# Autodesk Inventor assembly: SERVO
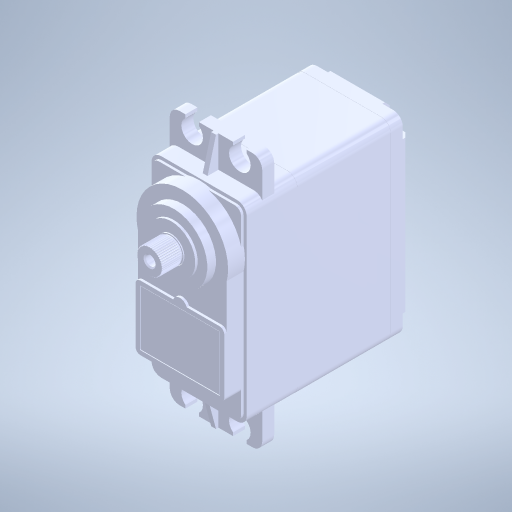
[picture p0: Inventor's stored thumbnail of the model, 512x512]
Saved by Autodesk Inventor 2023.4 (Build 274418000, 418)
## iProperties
Created: 2014-01
Part Number: SERVO
Description: SolidWorks IGES file using NURBS representation for surfaces
Document SubType Name: Assembly
Designer: mel
Title: C:\Users\Utente\Desktop\SERVO.IGS
Author: Utente
Sending System: SolidWorks 2012
Preprocessor: SolidWorks 2012
Minimum Resolution: 0.0
Sending System Product ID: SERVO.SLDASM
Receiving System Product ID: SERVO.SLDASM
Sent Units: Millimeter
Translation Standard: IGES 5.3
Model Creation Time: 2014-01-11
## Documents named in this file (3)
- D:\travail\année 2023-2024\IT\char à voile\hitec-hs-485hb-1.snapshot.2\SERVO\SERVO.iam
- D:\travail\année 2023-2024\IT\char à voile\hitec-hs-485hb-1.snapshot.2\SERVO\SERVOMOTORE Hitec HS485-HB.ipt
- D:\travail\année 2023-2024\IT\char à voile\hitec-hs-485hb-1.snapshot.2\SERVO\Ingranaggio dentato innesto servomotore.ipt
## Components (2 placed, 2 different names)
1. SERVOMOTORE Hitec HS485-HB
2. Ingranaggio dentato innesto servomotore
